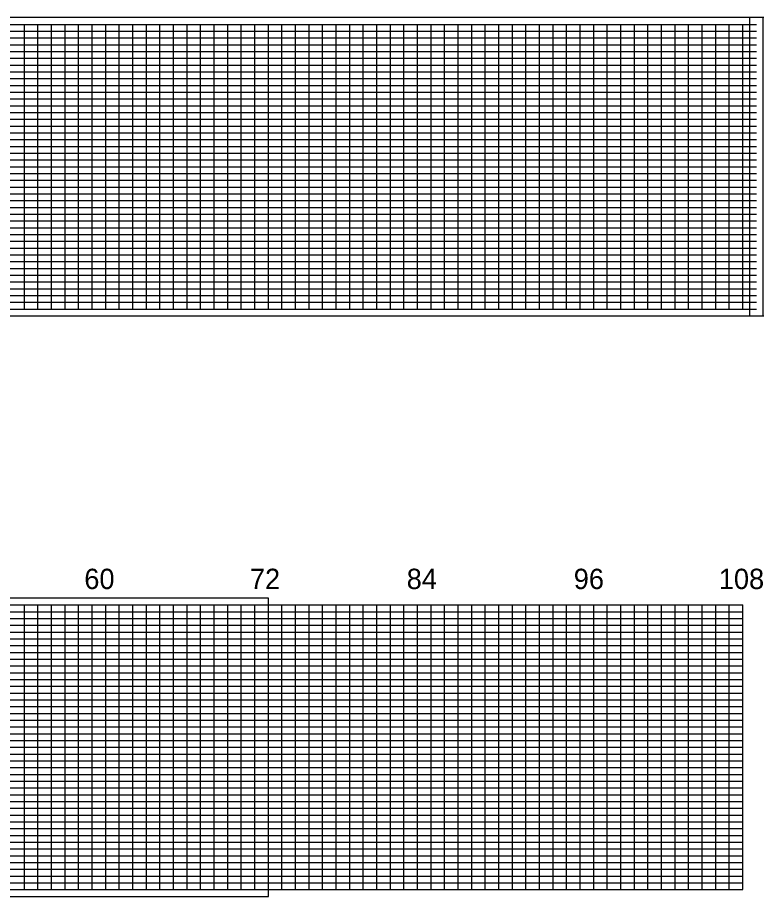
# Model space of a CAD drawing. Extents: x 1873632 to 1926512, y 813126 to 836257.
# Drawn here: x 1880938 to 1883663, y 815817 to 819059 of the extents above; entities that cross this region are included whole.
import ezdxf

# ---------------------------------------------------------------- set-up
doc = ezdxf.new("R2010")
doc.units = 0
doc.layers.add('RD_PD_WallFill', color=7, linetype='Continuous')
doc.layers.add('RD_SHT_IplotShp', color=7, linetype='Continuous')

msp = doc.modelspace()

# ---------------------------------------------------------------- linework, layer by layer
at = {"layer": 'RD_PD_WallFill'}
for p, q in [((1878313.1, 819033.6), (1883663.1, 819033.6)), ((1880963.1, 817983.6), (1880963.1, 819033.6)), ((1881013.1, 817983.6), (1881013.1, 819033.6)), ((1881063.1, 817983.6), (1881063.1, 819033.6)), ((1881113.1, 817983.6), (1881113.1, 819033.6)), ((1881163.1, 817983.6), (1881163.1, 819033.6)), ((1881213.1, 817983.6), (1881213.1, 819033.6)), ((1881263.1, 817983.6), (1881263.1, 819033.6)), ((1881313.1, 817983.6), (1881313.1, 819033.6)), ((1881363.1, 817983.6), (1881363.1, 819033.6)), ((1881413.1, 817983.6), (1881413.1, 819033.6)), ((1881463.1, 817983.6), (1881463.1, 819033.6)), ((1881513.1, 817983.6), (1881513.1, 819033.6)), ((1881563.1, 817983.6), (1881563.1, 819033.6)), ((1881613.1, 817983.6), (1881613.1, 819033.6)), ((1881663.1, 817983.6), (1881663.1, 819033.6)), ((1881713.1, 817983.6), (1881713.1, 819033.6)), ((1881763.1, 817983.6), (1881763.1, 819033.6)), ((1881813.1, 817983.6), (1881813.1, 819033.6)), ((1881863.1, 817983.6), (1881863.1, 819033.6)), ((1881913.1, 817983.6), (1881913.1, 819033.6)), ((1881963.1, 817983.6), (1881963.1, 819033.6)), ((1882013.1, 817983.6), (1882013.1, 819033.6)), ((1882063.1, 817983.6), (1882063.1, 819033.6)), ((1882113.1, 817983.6), (1882113.1, 819033.6)), ((1882163.1, 817983.6), (1882163.1, 819033.6)), ((1882213.1, 817983.6), (1882213.1, 819033.6)), ((1882263.1, 817983.6), (1882263.1, 819033.6)), ((1882313.1, 817983.6), (1882313.1, 819033.6)), ((1882363.1, 817983.6), (1882363.1, 819033.6)), ((1882413.1, 817983.6), (1882413.1, 819033.6)), ((1882463.1, 817983.6), (1882463.1, 819033.6)), ((1882513.1, 817983.6), (1882513.1, 819033.6)), ((1882563.1, 817983.6), (1882563.1, 819033.6)), ((1882613.1, 817983.6), (1882613.1, 819033.6)), ((1882663.1, 817983.6), (1882663.1, 819033.6)), ((1882713.1, 817983.6), (1882713.1, 819033.6)), ((1882763.1, 817983.6), (1882763.1, 819033.6)), ((1882813.1, 817983.6), (1882813.1, 819033.6)), ((1882863.1, 817983.6), (1882863.1, 819033.6)), ((1882913.1, 817983.6), (1882913.1, 819033.6)), ((1882963.1, 817983.6), (1882963.1, 819033.6)), ((1883013.1, 817983.6), (1883013.1, 819033.6)), ((1883063.1, 817983.6), (1883063.1, 819033.6)), ((1883113.1, 817983.6), (1883113.1, 819033.6)), ((1883163.1, 817983.6), (1883163.1, 819033.6)), ((1883213.1, 817983.6), (1883213.1, 819033.6)), ((1883263.1, 817983.6), (1883263.1, 819033.6)), ((1883313.1, 817983.6), (1883313.1, 819033.6)), ((1883363.1, 817983.6), (1883363.1, 819033.6)), ((1883413.1, 817983.6), (1883413.1, 819033.6)), ((1883463.1, 817983.6), (1883463.1, 819033.6)), ((1883513.1, 817983.6), (1883513.1, 819033.6)), ((1883563.1, 817983.6), (1883563.1, 819033.6)), ((1883613.1, 817983.6), (1883613.1, 819033.6)), ((1878763.1, 819008.6), (1883663.1, 819008.6)), ((1878763.1, 818983.6), (1883663.1, 818983.6)), ((1878763.1, 818958.6), (1883663.1, 818958.6)), ((1878763.1, 818933.6), (1883663.1, 818933.6)), ((1878763.1, 818908.6), (1883663.1, 818908.6)), ((1878313.1, 818883.6), (1883663.1, 818883.6)), ((1878313.1, 818858.6), (1883663.1, 818858.6)), ((1878313.1, 818833.6), (1883663.1, 818833.6)), ((1878313.1, 818808.6), (1883663.1, 818808.6)), ((1878313.1, 818783.6), (1883663.1, 818783.6)), ((1878313.1, 818758.6), (1883663.1, 818758.6)), ((1878313.1, 818733.6), (1883663.1, 818733.6)), ((1878313.1, 818708.6), (1883663.1, 818708.6)), ((1878313.1, 818683.6), (1883663.1, 818683.6)), ((1878313.1, 818658.6), (1883663.1, 818658.6)), ((1878313.1, 818633.6), (1883663.1, 818633.6)), ((1878313.1, 818608.6), (1883663.1, 818608.6)), ((1878313.1, 818583.6), (1883663.1, 818583.6)), ((1878313.1, 818558.6), (1883663.1, 818558.6)), ((1878313.1, 818533.6), (1883663.1, 818533.6)), ((1878313.1, 818508.6), (1883663.1, 818508.6)), ((1878313.1, 818483.6), (1883663.1, 818483.6)), ((1878313.1, 818458.6), (1883663.1, 818458.6)), ((1878313.1, 818433.6), (1883663.1, 818433.6)), ((1878313.1, 818408.6), (1883663.1, 818408.6)), ((1878313.1, 818383.6), (1883663.1, 818383.6)), ((1878313.1, 818358.6), (1883663.1, 818358.6)), ((1878313.1, 818333.6), (1883663.1, 818333.6)), ((1878313.1, 818308.6), (1883663.1, 818308.6)), ((1878313.1, 818283.6), (1883663.1, 818283.6)), ((1878313.1, 818258.6), (1883663.1, 818258.6)), ((1878313.1, 818233.6), (1883663.1, 818233.6)), ((1878313.1, 818208.6), (1883663.1, 818208.6)), ((1878313.1, 818183.6), (1883663.1, 818183.6)), ((1878313.1, 818158.6), (1883663.1, 818158.6)), ((1878313.1, 818133.6), (1883663.1, 818133.6)), ((1878313.1, 818108.6), (1883663.1, 818108.6)), ((1878313.1, 818083.6), (1883663.1, 818083.6)), ((1878313.1, 818058.6), (1883663.1, 818058.6)), ((1878313.1, 818033.6), (1883663.1, 818033.6)), ((1878363.1, 818008.6), (1883663.1, 818008.6)), ((1878313.1, 817983.6), (1883663.1, 817983.6)), ((1878263.1, 816892.1), (1883613.1, 816892.1)), ((1880963.1, 815842.1), (1880963.1, 816892.1)), ((1881013.1, 815842.1), (1881013.1, 816892.1)), ((1881063.1, 815842.1), (1881063.1, 816892.1)), ((1881113.1, 815842.1), (1881113.1, 816892.1)), ((1881163.1, 815842.1), (1881163.1, 816892.1)), ((1881213.1, 815842.1), (1881213.1, 816892.1)), ((1881263.1, 815842.1), (1881263.1, 816892.1)), ((1881313.1, 815842.1), (1881313.1, 816892.1)), ((1881363.1, 815842.1), (1881363.1, 816892.1)), ((1881413.1, 815842.1), (1881413.1, 816892.1)), ((1881463.1, 815842.1), (1881463.1, 816892.1)), ((1881513.1, 815842.1), (1881513.1, 816892.1)), ((1881563.1, 815842.1), (1881563.1, 816892.1)), ((1881613.1, 815842.1), (1881613.1, 816892.1)), ((1881663.1, 815842.1), (1881663.1, 816892.1)), ((1881713.1, 815842.1), (1881713.1, 816892.1)), ((1881763.1, 815842.1), (1881763.1, 816892.1)), ((1881813.1, 815842.1), (1881813.1, 816892.1)), ((1881863.1, 815842.1), (1881863.1, 816892.1)), ((1881913.1, 815842.1), (1881913.1, 816892.1)), ((1881963.1, 815842.1), (1881963.1, 816892.1)), ((1882013.1, 815842.1), (1882013.1, 816892.1)), ((1882063.1, 815842.1), (1882063.1, 816892.1)), ((1882113.1, 815842.1), (1882113.1, 816892.1)), ((1882163.1, 815842.1), (1882163.1, 816892.1)), ((1882213.1, 815842.1), (1882213.1, 816892.1)), ((1882263.1, 815842.1), (1882263.1, 816892.1)), ((1882313.1, 815842.1), (1882313.1, 816892.1)), ((1882363.1, 815842.1), (1882363.1, 816892.1)), ((1882413.1, 815842.1), (1882413.1, 816892.1)), ((1882463.1, 815842.1), (1882463.1, 816892.1)), ((1882513.1, 815842.1), (1882513.1, 816892.1)), ((1882563.1, 815842.1), (1882563.1, 816892.1)), ((1882613.1, 815842.1), (1882613.1, 816892.1)), ((1882663.1, 815842.1), (1882663.1, 816892.1)), ((1882713.1, 815842.1), (1882713.1, 816892.1)), ((1882763.1, 815842.1), (1882763.1, 816892.1)), ((1882813.1, 815842.1), (1882813.1, 816892.1)), ((1882863.1, 815842.1), (1882863.1, 816892.1)), ((1882913.1, 815842.1), (1882913.1, 816892.1)), ((1882963.1, 815842.1), (1882963.1, 816892.1)), ((1883013.1, 815842.1), (1883013.1, 816892.1)), ((1883063.1, 815842.1), (1883063.1, 816892.1)), ((1883113.1, 815842.1), (1883113.1, 816892.1)), ((1883163.1, 815842.1), (1883163.1, 816892.1)), ((1883213.1, 815842.1), (1883213.1, 816892.1)), ((1883263.1, 815842.1), (1883263.1, 816892.1)), ((1883313.1, 815842.1), (1883313.1, 816892.1)), ((1883363.1, 815842.2), (1883363.1, 816892.1)), ((1883413.1, 815842.1), (1883413.1, 816892.1)), ((1883463.1, 815842.1), (1883463.1, 816892.1)), ((1883513.1, 815842.1), (1883513.1, 816892.1)), ((1883563.1, 815842.1), (1883563.1, 816892.1)), ((1883613.1, 815842.1), (1883613.1, 816892.1)), ((1878713.1, 816867.1), (1883613.1, 816867.1)), ((1878713.1, 816842.1), (1883613.1, 816842.1)), ((1878713.1, 816817.1), (1883613.1, 816817.1)), ((1878713.1, 816792.1), (1883613.1, 816792.1)), ((1878713.1, 816767.1), (1883613.1, 816767.1)), ((1878263.1, 816742.1), (1883613.1, 816742.1)), ((1878263.1, 816717.1), (1883613.1, 816717.1)), ((1878263.1, 816692.1), (1883613.1, 816692.1)), ((1878263.1, 816667.1), (1883613.1, 816667.1)), ((1878263.1, 816642.1), (1883613.1, 816642.1)), ((1878263.1, 816617.1), (1883613.1, 816617.1)), ((1878263.1, 816592.1), (1883613.1, 816592.1)), ((1878263.1, 816567.1), (1883613.1, 816567.1)), ((1878263.1, 816542.1), (1883613.1, 816542.1)), ((1878263.1, 816517.1), (1883613.1, 816517.1)), ((1878263.1, 816492.1), (1883613.1, 816492.1)), ((1878263.1, 816467.1), (1883613.1, 816467.1)), ((1878263.1, 816442.1), (1883613.1, 816442.1)), ((1878263.1, 816417.1), (1883613.1, 816417.1)), ((1878263.1, 816392.1), (1883613.1, 816392.1)), ((1878263.1, 816367.1), (1883613.1, 816367.1)), ((1878263.1, 816342.1), (1883613.1, 816342.1)), ((1878263.1, 816317.1), (1883613.1, 816317.1)), ((1878263.1, 816292.1), (1883613.1, 816292.1)), ((1878263.1, 816267.1), (1883613.1, 816267.1)), ((1878263.1, 816242.1), (1883613.1, 816242.1)), ((1878263.1, 816217.1), (1883613.1, 816217.1)), ((1878263.1, 816192.1), (1883613.1, 816192.1)), ((1878263.1, 816167.1), (1883613.1, 816167.1)), ((1878263.1, 816142.1), (1883613.1, 816142.1)), ((1878263.1, 816117.1), (1883613.1, 816117.1)), ((1878263.1, 816092.1), (1883613.1, 816092.1)), ((1878263.1, 816067.1), (1883613.1, 816067.1)), ((1878263.1, 816042.1), (1883613.1, 816042.1)), ((1878263.1, 816017.1), (1883613.1, 816017.1)), ((1878263.1, 815992.1), (1883613.1, 815992.1)), ((1878263.1, 815967.1), (1883613.1, 815967.1)), ((1878263.1, 815942.1), (1883613.1, 815942.1)), ((1878263.1, 815917.1), (1883613.1, 815917.1)), ((1878263.1, 815892.1), (1883613.1, 815892.1)), ((1878313.1, 815867.1), (1883613.1, 815867.1)), ((1878263.1, 815842.1), (1883613.1, 815842.1))]:
    msp.add_line(p, q, dxfattribs=at)
at = {"layer": 'RD_SHT_IplotShp'}
for points in [[(1878288.1, 817958.6), (1883688.1, 817958.6), (1883688.1, 819058.6), (1878288.1, 819058.6)], [(1883638.1, 817958.6), (1885388.1, 817958.6), (1885388.1, 819058.6), (1883638.1, 819058.6)], [(1878238.1, 815817.1), (1881863.1, 815817.1), (1881863.1, 816917.1), (1878238.1, 816917.1)]]:
    msp.add_lwpolyline(points, close=True, dxfattribs=at)

# ---------------------------------------------------------------- texts
at = {"layer": 'RD_PD_WallFill'}
for s, p in [('60', (1881184.2, 816950.8)), ('72', (1881794.9, 816950.8)), ('84', (1882373.2, 816950.8)), ('96', (1882989.3, 816950.8)), ('108', (1883524.3, 816950.8))]:
    msp.add_text(s, height=75, dxfattribs=at).set_placement(p)

doc.saveas('drawing.dxf')
